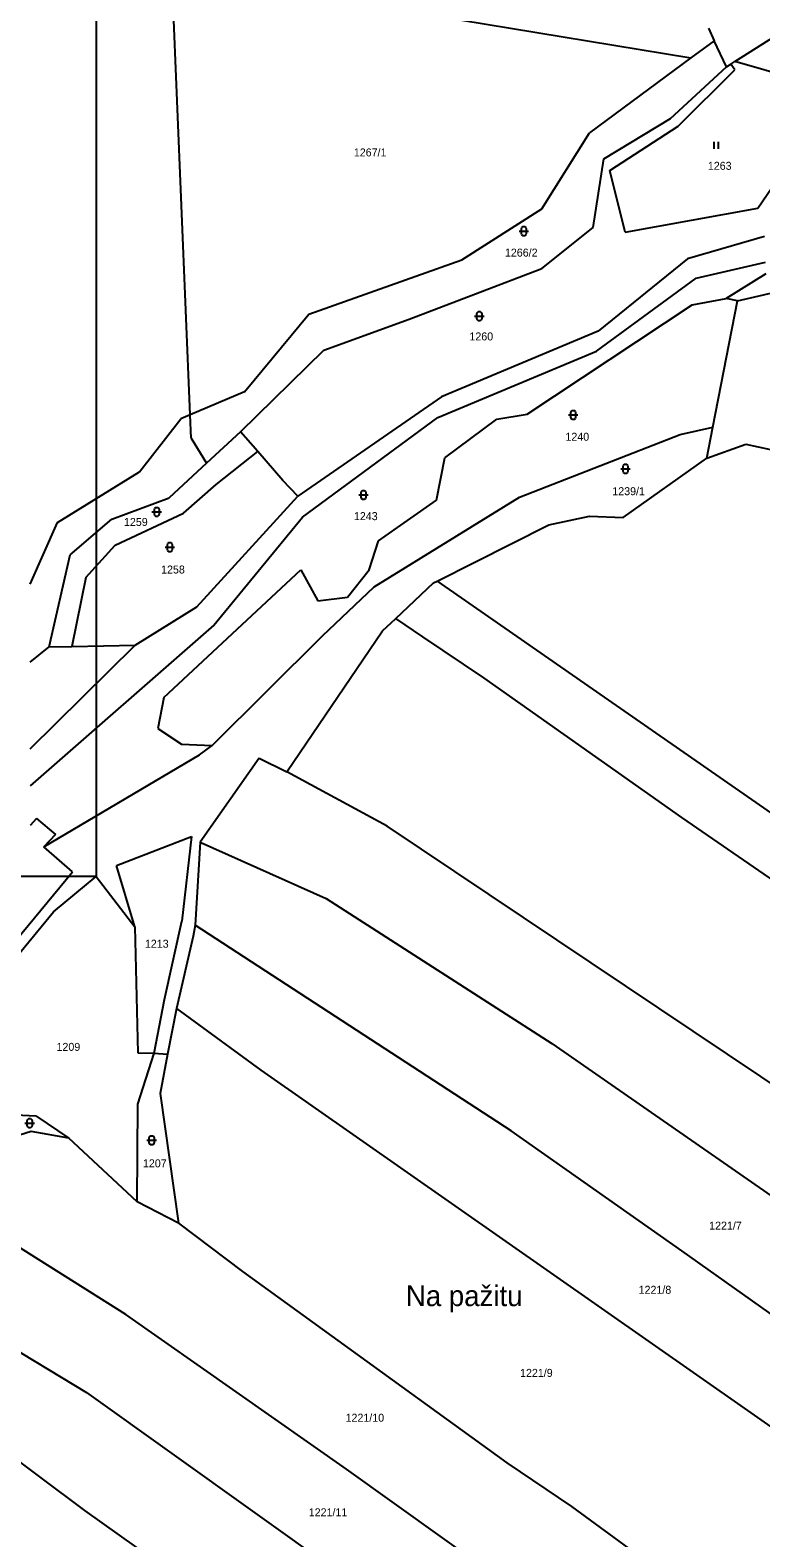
# Model space of a CAD drawing. Extents: x -799786 to -795190, y -1021716 to -1017834.
# Drawn here: x -798434.2 to -798278.5, y -1019350.1 to -1019029 of the extents above; entities that cross this region are included whole.
import ezdxf

# ---------------------------------------------------------------- set-up
doc = ezdxf.new("R2010")
doc.units = 0
for name, color, linetype in [('Default', 7, 'Continuous'), ('KN_HRANICE', 7, 'Continuous'), ('KN_KULTURY', 7, 'Continuous'), ('KN_PARCELY', 7, 'Continuous'), ('LEGENDA', 7, 'Continuous')]:
    doc.layers.add(name, color=color, linetype=linetype)

# ---------------------------------------------------------------- blocks, each defined once
blk = doc.blocks.new('306')
at = {"layer": 'Default'}
for p, q in [((-0.5, 1.5), (-0.5, 0)), ((0.5, 0), (0.5, 1.5))]:
    blk.add_line(p, q, dxfattribs=at)
blk = doc.blocks.new('316')
at = {"layer": 'Default'}
for points in [[(-1, 1), (0.27, 1), (1, 1)], [(-0.5, 1.5), (-0.4, 1.79), (-0.15, 1.97), (0.16, 1.97), (0.41, 1.79), (0.51, 1.5), (0.51, 0.5), (0.41, 0.21), (0.16, 0.03), (-0.15, 0.03), (-0.4, 0.21), (-0.5, 0.5), (-0.5, 1.5)]]:
    blk.add_lwpolyline(points, dxfattribs=at)

msp = doc.modelspace()

# ---------------------------------------------------------------- linework, layer by layer
at = {"layer": 'KN_HRANICE'}
for p, q in [((-798400.12, -1019110.95), (-798404.09, -1019014.54)), ((-798359.05, -1019024.1), (-798293.45, -1019034.91)), ((-798289.67, -1019028.59), (-798288.5, -1019031.25)), ((-798284.03, -1019035.68), (-798271.37, -1019027.66)), ((-798288.5, -1019031.25), (-798293.45, -1019034.91)), ((-798285.82, -1019036.77), (-798288.5, -1019031.25)), ((-798293.45, -1019034.91), (-798315.04, -1019050.85)), ((-798297.8, -1019047.77), (-798285.82, -1019036.77)), ((-798296.11, -1019049.46), (-798284.03, -1019037.42)), ((-798285.82, -1019036.77), (-798284.92, -1019036.23)), ((-798284.92, -1019036.23), (-798284.03, -1019035.68)), ((-798284.03, -1019037.42), (-798284.92, -1019036.23)), ((-798268.28, -1019040.2), (-798284.03, -1019035.68)), ((-798311.96, -1019056.41), (-798297.8, -1019047.77)), ((-798325.18, -1019067.07), (-798315.04, -1019050.85)), ((-798310.72, -1019058.9), (-798296.11, -1019049.46)), ((-798279.13, -1019066.87), (-798269.48, -1019052.64)), ((-798314.25, -1019070.99), (-798311.96, -1019056.41)), ((-798307.44, -1019071.99), (-798310.72, -1019058.9)), ((-798342.22, -1019077.92), (-798325.18, -1019067.07)), ((-798307.44, -1019071.99), (-798279.13, -1019066.87)), ((-798325.18, -1019079.73), (-798314.25, -1019070.99)), ((-798277.73, -1019072.94), (-798294.15, -1019077.72)), ((-798374.85, -1019089.46), (-798342.22, -1019077.92)), ((-798353.46, -1019090.56), (-798325.18, -1019079.73)), ((-798294.15, -1019077.72), (-798313.2, -1019093.11)), ((-798292.31, -1019081.83), (-798277.52, -1019078.42)), ((-798313.51, -1019097.35), (-798292.31, -1019081.83)), ((-798277.42, -1019080.9), (-798285.9, -1019086.17)), ((-798293.14, -1019087.52), (-798285.9, -1019086.17)), ((-798283.51, -1019086.63), (-798285.9, -1019086.17)), ((-798283.51, -1019086.63), (-798272.14, -1019083.99)), ((-798388.54, -1019106.05), (-798374.85, -1019089.46)), ((-798328.29, -1019110.8), (-798293.14, -1019087.52)), ((-798288.76, -1019113.55), (-798283.51, -1019086.63)), ((-798371.66, -1019097.13), (-798353.46, -1019090.56)), ((-798313.2, -1019093.11), (-798346.6, -1019107.08)), ((-798389.43, -1019114.51), (-798371.66, -1019097.13)), ((-798347.32, -1019111.52), (-798313.51, -1019097.35)), ((-798388.54, -1019106.05), (-798400.12, -1019110.95)), ((-798346.6, -1019107.08), (-798377.17, -1019128.23)), ((-798410.89, -1019123.09), (-798402.14, -1019111.8)), ((-798400.12, -1019110.95), (-798402.14, -1019111.8)), ((-798399.92, -1019115.9), (-798400.12, -1019110.95)), ((-798376.17, -1019132.7), (-798347.32, -1019111.52)), ((-798345.85, -1019120.08), (-798334.81, -1019111.83)), ((-798334.81, -1019111.83), (-798328.29, -1019110.8)), ((-798389.43, -1019114.51), (-798396.65, -1019121.23)), ((-798385.72, -1019118.74), (-798389.43, -1019114.51)), ((-798329.93, -1019128.46), (-798295.7, -1019115.11)), ((-798295.7, -1019115.11), (-798288.76, -1019113.55)), ((-798290.05, -1019120.17), (-798288.76, -1019113.55)), ((-798399.92, -1019115.9), (-798396.65, -1019121.23)), ((-798290.05, -1019120.17), (-798281.71, -1019117.15)), ((-798281.71, -1019117.15), (-798270.95, -1019119.48)), ((-798396.65, -1019121.23), (-798404.61, -1019128.63)), ((-798394.6, -1019125.76), (-798385.72, -1019118.74)), ((-798380.38, -1019124.89), (-798385.72, -1019118.74)), ((-798347.61, -1019129.08), (-798345.85, -1019120.08)), ((-798307.85, -1019132.82), (-798290.05, -1019120.17)), ((-798428.38, -1019133.84), (-798410.89, -1019123.09)), ((-798377.17, -1019128.23), (-798380.38, -1019124.89)), ((-798401.54, -1019131.84), (-798394.6, -1019125.76)), ((-798416.83, -1019133.17), (-798404.61, -1019128.63)), ((-798398.71, -1019151.85), (-798377.17, -1019128.23)), ((-798360.92, -1019147.57), (-798329.93, -1019128.46)), ((-798359.99, -1019137.74), (-798347.61, -1019129.08)), ((-798434.21, -1019146.97), (-798428.38, -1019133.84)), ((-798425.69, -1019140.76), (-798416.83, -1019133.17)), ((-798416.1, -1019138.65), (-798401.54, -1019131.84)), ((-798395.06, -1019155.75), (-798376.17, -1019132.7)), ((-798347.52, -1019146.35), (-798323.68, -1019134.33)), ((-798323.68, -1019134.33), (-798315, -1019132.53)), ((-798315, -1019132.53), (-798307.85, -1019132.82)), ((-798361.95, -1019143.95), (-798359.99, -1019137.74)), ((-798430.16, -1019160.33), (-798425.69, -1019140.76)), ((-798422.35, -1019145.57), (-798416.1, -1019138.65)), ((-798405.77, -1019171.12), (-798376.53, -1019143.95)), ((-798376.53, -1019143.95), (-798372.91, -1019150.57)), ((-798366.6, -1019149.74), (-798361.95, -1019143.95)), ((-798422.35, -1019145.57), (-798425.35, -1019160.26)), ((-798356.31, -1019154.31), (-798348.29, -1019146.68)), ((-798348.29, -1019146.68), (-798347.52, -1019146.35)), ((-798347.52, -1019146.35), (-798176.91, -1019264.88)), ((-798372.91, -1019150.57), (-798366.6, -1019149.74)), ((-798371.95, -1019157.98), (-798360.92, -1019147.57)), ((-798411.87, -1019160), (-798398.71, -1019151.85)), ((-798395.06, -1019155.75), (-798434.21, -1019189.94)), ((-798379.56, -1019186.95), (-798359.11, -1019156.9)), ((-798359.11, -1019156.9), (-798356.31, -1019154.31)), ((-798350.55, -1019158.22), (-798356.31, -1019154.31)), ((-798434.21, -1019182.07), (-798411.87, -1019160)), ((-798430.16, -1019160.33), (-798425.35, -1019160.26)), ((-798425.35, -1019160.26), (-798411.87, -1019160)), ((-798395.43, -1019181.36), (-798371.95, -1019157.98)), ((-798337.52, -1019166.91), (-798350.55, -1019158.22)), ((-798434.21, -1019163.57), (-798430.16, -1019160.33)), ((-798295.35, -1019196.67), (-798337.52, -1019166.91)), ((-798405.77, -1019171.12), (-798407.01, -1019177.74)), ((-798407.01, -1019177.74), (-798401.94, -1019181.05)), ((-798401.94, -1019181.05), (-798395.43, -1019181.36)), ((-798398.13, -1019183.37), (-798395.43, -1019181.36)), ((-798431.28, -1019202.97), (-798398.13, -1019183.37)), ((-798385.45, -1019184.05), (-798397.97, -1019201.95)), ((-798385.45, -1019184.05), (-798379.56, -1019186.95)), ((-798358.17, -1019198.54), (-798379.56, -1019186.95)), ((-798432.88, -1019196.92), (-798434.21, -1019198.43)), ((-798432.88, -1019196.92), (-798428.85, -1019200.33)), ((-798269.58, -1019257.87), (-798358.17, -1019198.54)), ((-798236.26, -1019237.37), (-798295.35, -1019196.67)), ((-798428.85, -1019200.33), (-798431.28, -1019202.97)), ((-798415.85, -1019206.94), (-798399.81, -1019200.77)), ((-798399.81, -1019200.77), (-798401.87, -1019218.77)), ((-798397.97, -1019201.95), (-798399.08, -1019219.6)), ((-798397.97, -1019201.95), (-798371.17, -1019213.94)), ((-798425.19, -1019208.25), (-798431.28, -1019202.97)), ((-798458.53, -1019248.28), (-798425.19, -1019208.25)), ((-798411.9, -1019220.01), (-798415.85, -1019206.94)), ((-798429.28, -1019216.81), (-798420.18, -1019209.26)), ((-798420.18, -1019209.26), (-798411.9, -1019220.01)), ((-798371.17, -1019213.94), (-798323.08, -1019244.85)), ((-798456.62, -1019249.78), (-798429.28, -1019216.81)), ((-798411.9, -1019220.01), (-798411.26, -1019246.84)), ((-798405.6, -1019235.43), (-798401.87, -1019218.77)), ((-798399.08, -1019219.6), (-798399.5, -1019221.98)), ((-798331.7, -1019263.44), (-798399.08, -1019219.6)), ((-798399.5, -1019221.98), (-798403.01, -1019237.4)), ((-798407.77, -1019246.91), (-798405.6, -1019235.43)), ((-798403.01, -1019237.4), (-798404.98, -1019247.1)), ((-798403.01, -1019237.4), (-798385.05, -1019250.48)), ((-798411.28, -1019257.77), (-798407.77, -1019246.91)), ((-798411.26, -1019246.84), (-798407.77, -1019246.91)), ((-798407.77, -1019246.91), (-798404.98, -1019247.1)), ((-798323.08, -1019244.85), (-798216.61, -1019318.7)), ((-798404.98, -1019247.1), (-798406.53, -1019255.48)), ((-798385.05, -1019250.48), (-798240.9, -1019351.36)), ((-798406.53, -1019255.48), (-798402.6, -1019283.09)), ((-798441.91, -1019259.81), (-798433.02, -1019260.22)), ((-798411.39, -1019278.54), (-798411.28, -1019257.77)), ((-798433.02, -1019260.22), (-798425.97, -1019264.99)), ((-798434, -1019263.58), (-798451.99, -1019269.12)), ((-798425.97, -1019264.99), (-798434, -1019263.58)), ((-798411.39, -1019278.54), (-798425.97, -1019264.99)), ((-798295.38, -1019289), (-798331.7, -1019263.44)), ((-798413.87, -1019302.58), (-798455.66, -1019276.2)), ((-798402.6, -1019283.09), (-798411.39, -1019278.54)), ((-798402.6, -1019283.09), (-798388.96, -1019293.42)), ((-798172.28, -1019376.09), (-798295.38, -1019289)), ((-798388.96, -1019293.42), (-798332.63, -1019334.12)), ((-798458.48, -1019297.36), (-798422.2, -1019319.14)), ((-798366.78, -1019335.52), (-798413.87, -1019302.58)), ((-798422.56, -1019344.32), (-798456.65, -1019318.8)), ((-798422.2, -1019319.14), (-798299.96, -1019406.46)), ((-798267.29, -1019406.58), (-798366.78, -1019335.52)), ((-798332.63, -1019334.12), (-798318.88, -1019343.43)), ((-798336.15, -1019405.61), (-798422.56, -1019344.32)), ((-798318.88, -1019343.43), (-798278.8, -1019372.75))]:
    msp.add_line(p, q, dxfattribs=at)
at = {"layer": 'LEGENDA'}
msp.add_lwpolyline([(-799014.18, -1018789.26), (-798420.18, -1018789.26), (-798420.18, -1019209.26), (-799014.18, -1019209.26)], close=True, dxfattribs=at)

# ---------------------------------------------------------------- block references
at = {"layer": 'KN_KULTURY'}
for name, p in [('306', (-798288.02, -1019054.24)), ('316', (-798329.03, -1019072.79)), ('316', (-798338.51, -1019090.9)), ('316', (-798318.49, -1019111.95)), ('316', (-798307.36, -1019123.42)), ('316', (-798363.18, -1019128.99)), ('316', (-798407.26, -1019132.6)), ('316', (-798404.46, -1019140.1)), ('316', (-798434.33, -1019262.8)), ('316', (-798408.33, -1019266.45))]:
    msp.add_blockref(name, p, dxfattribs=at)

# ---------------------------------------------------------------- texts
at = {"layer": 'KN_PARCELY'}
for s, height, p in [('1267/1', 1.7, (-798365.25, -1019055.88)), ('1263', 1.7, (-798289.81, -1019058.73)), ('1266/2', 1.7, (-798333.05, -1019077.22)), ('1260', 1.7, (-798340.62, -1019095.07)), ('1240', 1.7, (-798320.16, -1019116.44)), ('1239/1', 1.7, (-798310.17, -1019128.04)), ('1259', 1.7, (-798414.23, -1019134.59)), ('1243', 1.7, (-798365.23, -1019133.35)), ('1258', 1.7, (-798406.32, -1019144.72)), ('1213', 1.7, (-798409.77, -1019224.43)), ('1209', 1.7, (-798428.61, -1019246.4)), ('1207', 1.7, (-798410.19, -1019271.2)), ('1221/7', 1.7, (-798289.54, -1019284.48)), ('Na pažitu', 4.4, (-798354.16, -1019300.77)), ('1221/8', 1.7, (-798304.56, -1019298.14)), ('1221/9', 1.7, (-798329.83, -1019315.84)), ('1221/10', 1.7, (-798367.01, -1019325.39)), ('1221/11', 1.7, (-798374.86, -1019345.53))]:
    msp.add_text(s, height=height, dxfattribs=at).set_placement(p)

doc.saveas('drawing.dxf')
